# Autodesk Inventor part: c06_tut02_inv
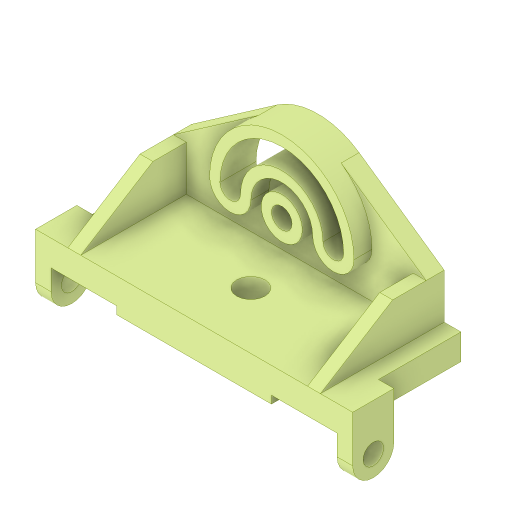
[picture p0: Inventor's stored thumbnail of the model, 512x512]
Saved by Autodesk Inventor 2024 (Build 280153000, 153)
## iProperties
Created: 2015-03
Part Number: c06_tut02_inv
Material: Generic
Document SubType Name: Modeling
Designer: Sandeep
Density: 1 g/cm^3
Appearance: Zinc Chromate 2
Author: Sandeep
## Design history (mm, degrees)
sketch "Sketch1"
  geometry: L1 (0, 0)-(-51, 0); L2 (-51, 0)-(-51, -6); L3 (-51, -6)-(-171, -6); L4 (-171, -6)-(-171, 0); L5 (-171, 0)-(-222, 0); L6 (-222, 0)-(-222, 20); L7 (-222, 20)-(0, 20); L8 (0, 20)-(0, 0)
  constraints: 16 end point, 6 perpendicular, 2 point on line, 1 horizontal
  dimensions: "d0" = 20 distance of L5.end L6.end; "d1" = 26 distance between parallel lines of L3 L7; "d2" = 120 distance of L4.end L1.end; "d3" = 51 distance between parallel lines of L2 L8; "d4" = 51 distance from line of L4.end L6
extrude "Extrusion1" new body sketch "Sketch1" distance "d5" = 96; taper "d6" = 0 deg
sketch "Sketch2"
  geometry: L1 (209, -20)-(209, -55); L2 (209, -55)-(143, -100.957); L3 (79, -100.957)-(13, -55); L4 (13, -55)-(13, -20); L5 (222, -20)-(0, -20) reference; L6 (13, -20)-(209, -20); L7 (222, -20)-(222, 0) reference; L8 (209, -55)-(-58.567, -55); A1 r 56 centre (111, -55) between (79, -100.957) and (143, -100.957); 1 further point
  constraints: 12 end point, 2 parallel, 2 point on circle, 2 point on line, 2 tangent, 1 centre point, 1 collinear, 1 horizontal, 1 vertical
  dimensions: "d7" = 13 distance from line of point (0, 0) L4; "d8" = 13 distance between parallel lines of L1 L7; "d10" = 56 radius of A1; "d11" = 98 distance from line of L1 A1.centre; "d13" = 35 distance of L1.start L1.end
extrude "Extrusion2" join sketch "Sketch2" distance "d14" = 14; taper "d15" = 0 deg
sketch "Sketch4"
  geometry: L1 (111, 55)-(-9.927, 55); C1 r 16 at (111, 55); A1 r 40 centre (111, 55) between (151, 55) and (71, 55); A2 r 56 centre (111, 55) between (167, 55) and (55, 55); A3 r 24 centre (111, 55) between (135, 55) and (87, 55); A4 r 16 centre (151, 55) between (135, 55) and (167, 55); A5 r 16 centre (71, 55) between (55, 55) and (87, 55); A6 r 56 centre (111, 55) between (143, 100.957) and (79, 100.957) reference
  constraints: 10 point on circle, 6 centre point, 4 tangent, 2 end point, 2 point on line, 1 coincident, 1 concentric, 1 horizontal
  dimensions: "d20" = 56 radius of A2; "d21" = 24 radius of A3; "d22" = 32 diameter of C1
extrude "Extrusion3" join sketch "Sketch4" distance "d23" = 14; taper "d24" = 0 deg
sketch "Sketch7"
  geometry: C1 r 8 at (111, 55); A1 r 16 centre (151, 55) between (135, 55) and (167, 55) reference; A2 r 16 centre (71, 55) between (55, 55) and (87, 55) reference; A3 r 40 centre (111, 55) between (151, 55) and (71, 55); A4 r 48 centre (111, 55) between (159, 55) and (63, 55); A5 r 32 centre (111, 55) between (143, 55) and (79, 55); A6 r 8 centre (151, 55) between (143, 55) and (159, 55); A7 r 8 centre (71, 55) between (63, 55) and (79, 55); A8 r 56 centre (111, 55) between (167, 55) and (55, 55) reference; 1 further point
  constraints: 10 point on circle, 6 centre point, 4 tangent, 1 coincident, 1 concentric
  dimensions: "d26" = 8 radius of A6; "d27" = 16 diameter of C1
extrude "Extrusion4" cut sketch "Sketch7" extent not by distance; stored distance "d28" = 14; taper "d29" = 0 deg
workplane "Work Plane1"
sketch "Sketch12"
  geometry: L1 (35, -96)-(35, 0) reference; L2 (35, -13.954)-(35, -96); L3 (35, -96)-(0, -40); L4 (0, -40)-(0, -14); L5 (0, 0)-(-45.957, 0) reference; 1 further point
  constraints: 6 end point, 1 collinear, 1 parallel, 1 point on line
  dimensions: "d34" = 35 distance between parallel lines of L1 L4; "d35" = 40 distance from line of L5 L3.end
feature "Rib1" sketch "Sketch12" dims "d36" = 1, "d37" = 10, "d38" = 0, "d39" = 0, "d40" = 1, "d41" = 1
sketch "Sketch14"
  geometry: L1 (0, 0)-(0, 32); L2 (0, 32)-(36, 32); L3 (36, 0)-(0, 0); L4 (0, 96)-(0, 0) reference; C1 r 8 at (36, 16); A1 r 16 centre (36, 16) between (36, 0) and (36, 32); 1 further point
  constraints: 6 end point, 2 centre point, 2 point on circle, 2 tangent, 1 coincident, 1 horizontal, 1 perpendicular, 1 point on line
  dimensions: "d42" = 36 distance from line of L1 A1.centre; "d43" = 16 radius of A1; "d44" = 16 diameter of C1
extrude "Extrusion5" join sketch "Sketch14" distance "d45" = 12; taper "d46" = 0 deg
workplane "Work Plane2"
mirror "Mirror1"
hole "Hole1" diameter "d50" = 22; stored, may be unused: countersink angle "d54" = 90 deg, drill point angle "d56" = 118 deg; dims "d48" = 88, "d49" = 38, "d51" = 6, "d52" = 4, "d53" = 2, "d55" = 8
body "Solid1"
other parameters: "d32" = 0, "d47" = -111
